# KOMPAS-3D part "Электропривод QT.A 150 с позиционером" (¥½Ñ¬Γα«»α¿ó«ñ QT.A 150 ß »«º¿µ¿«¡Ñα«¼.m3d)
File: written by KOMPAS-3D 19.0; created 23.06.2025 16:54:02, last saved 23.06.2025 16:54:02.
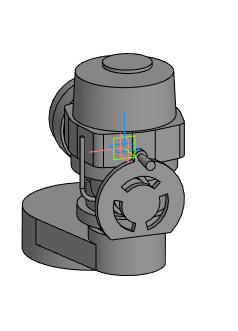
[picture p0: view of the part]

Document properties: Автор: Евгений; Полное имя файла: E:\Dendor Работа Сачек\3D для проектировщиков\3.5 Тип QT.А Электропривод\stp_Электропривод QT.A с позиционером\Электропривод QT.A 150 с позиционером.m3d

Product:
- Part/product: Электропривод QT.A 150 с позиционером

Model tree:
1. Операция без истории:1  (labels: Электропривод QT.A 150 с позиционером)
